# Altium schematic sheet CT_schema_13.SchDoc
size 388 x 278 mm
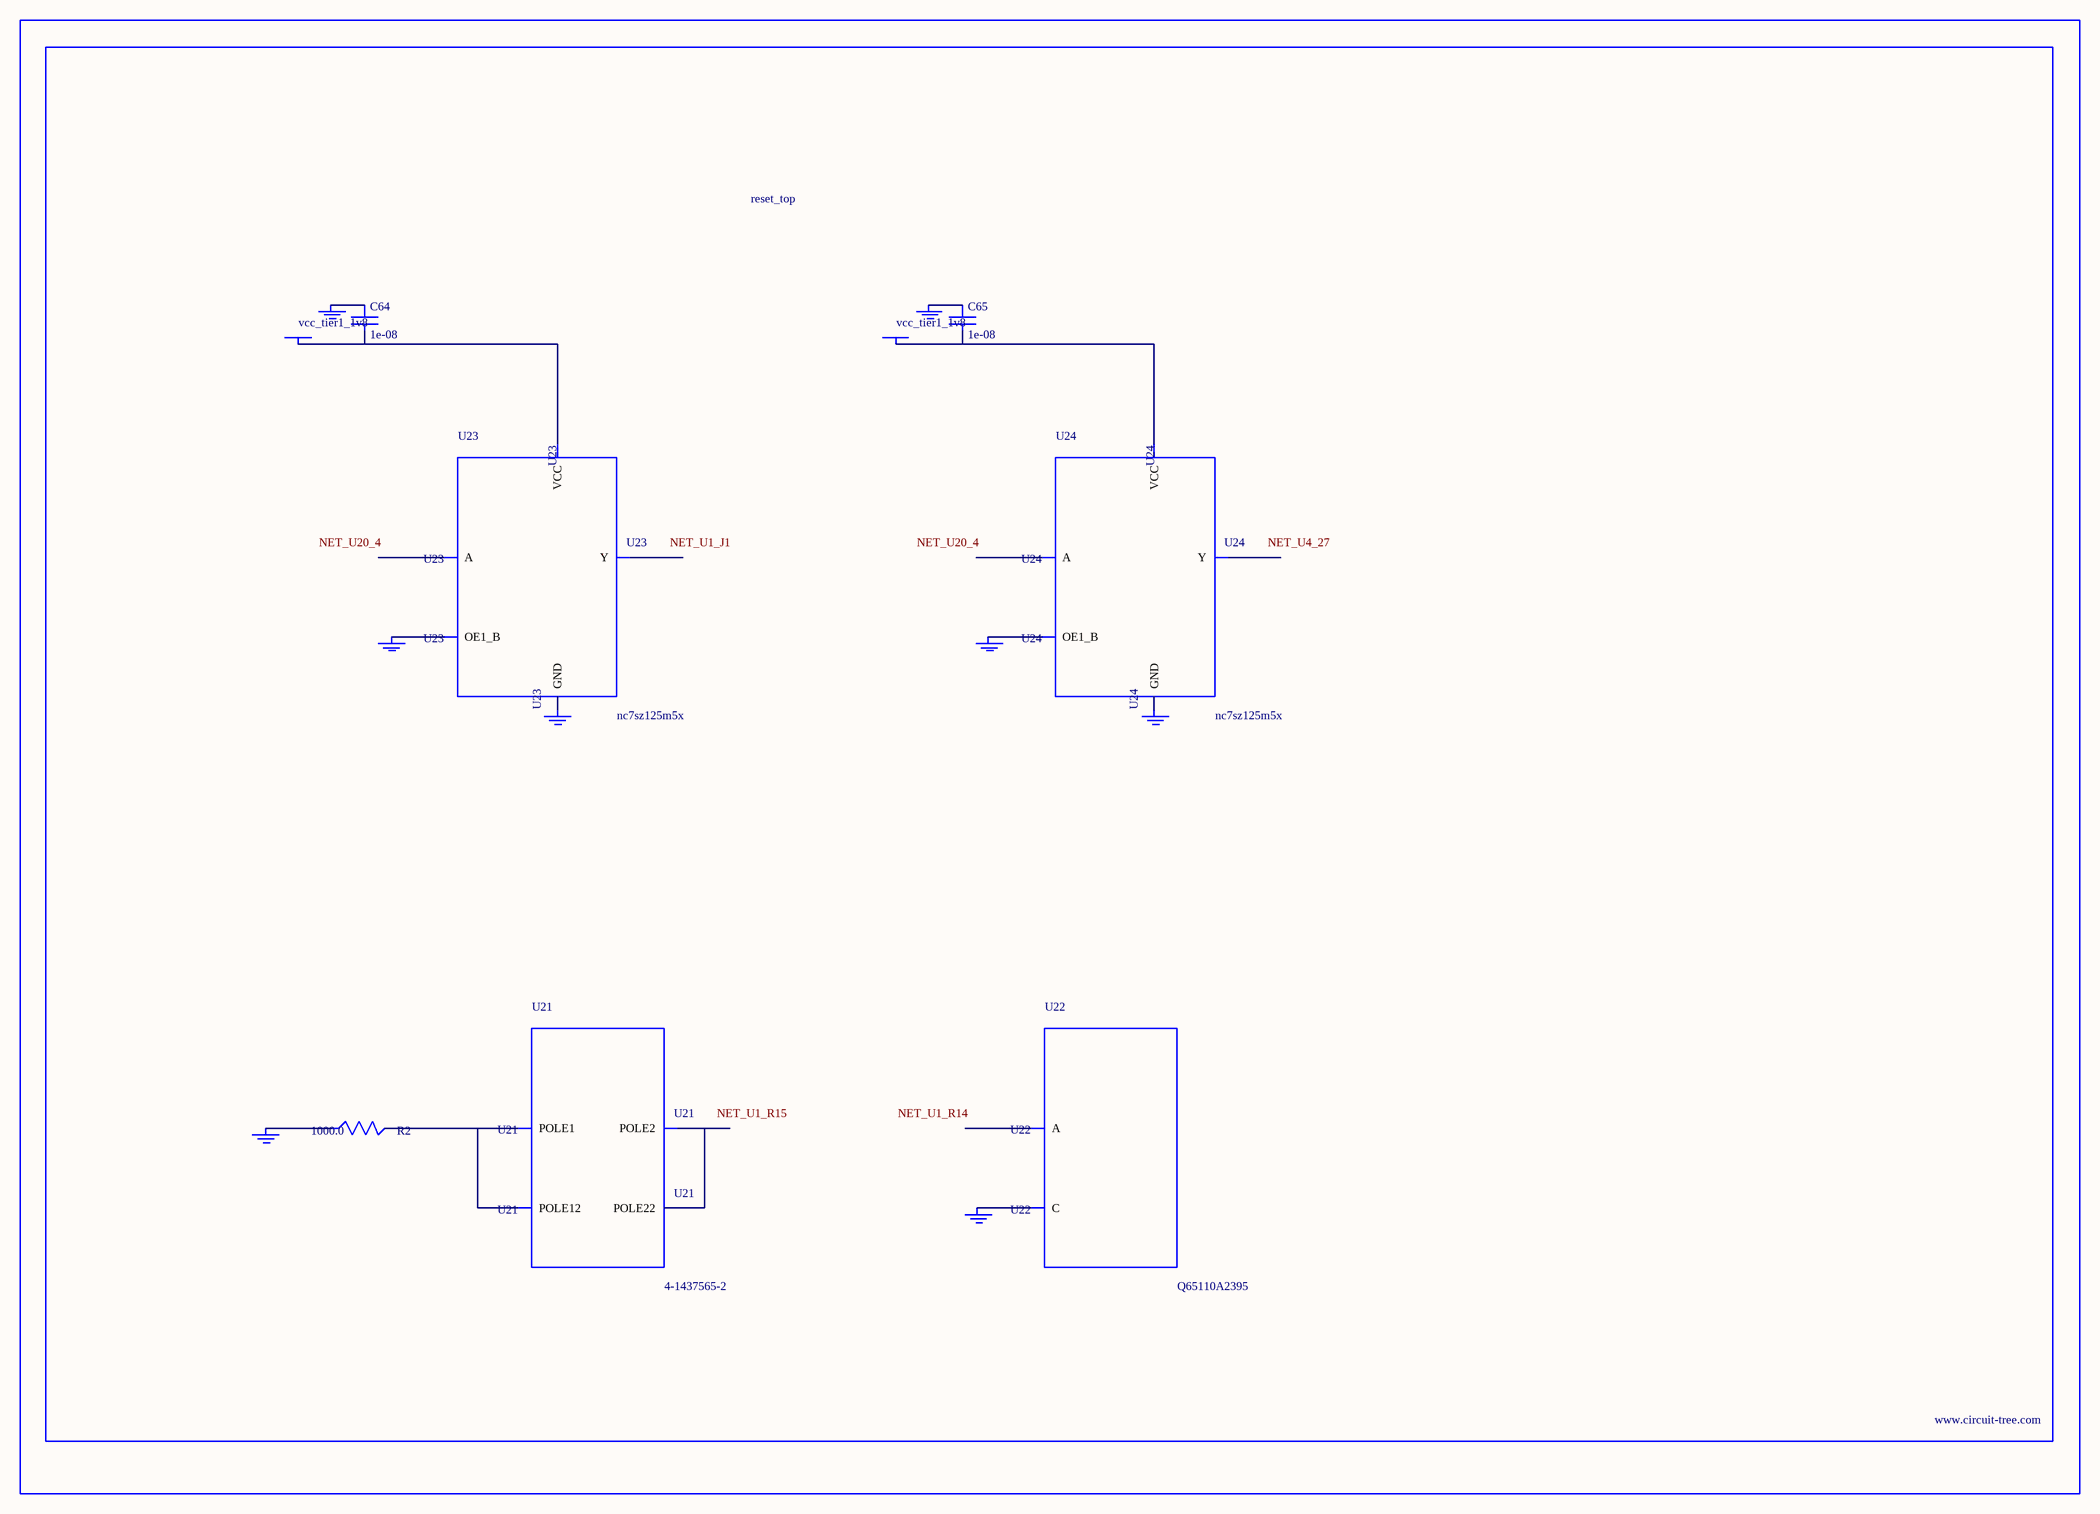
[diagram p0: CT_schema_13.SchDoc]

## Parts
BORDER12  (no value)
C64  1e-08  [C0402]
C65  1e-08  [C0402]
GND_INSTANCE_12_0  (no value)
GND_INSTANCE_12_1  (no value)
GND_INSTANCE_12_2  (no value)
GND_INSTANCE_12_3  (no value)
GND_INSTANCE_12_4  (no value)
GND_INSTANCE_12_5  (no value)
GND_INSTANCE_12_6  (no value)
GND_INSTANCE_12_7  (no value)
POWER_INSTANCE_12_0  vcc_tier1_1v8
POWER_INSTANCE_12_1  vcc_tier1_1v8
R2  1000.0  [R0603]
U21  4-1437565-2  [SW_4-1437565-2]
U22  Q65110A2395  [LGM67K-G1J2-24-Z]
U23  nc7sz125m5x  [NC7SZ125M5X]
U24  nc7sz125m5x  [NC7SZ125M5X]

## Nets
NetC64_1: C64.1 GND_INSTANCE_12_2.0(GND)
NetC64_2: C64.2 POWER_INSTANCE_12_0.0(PWR) U23.5(VCC)
NetC65_1: C65.1 GND_INSTANCE_12_5.0(GND)
NetC65_2: C65.2 POWER_INSTANCE_12_1.0(PWR) U24.5(VCC)
NetGND_INSTANCE_12_0_0: GND_INSTANCE_12_0.0(GND) R2.1
NetGND_INSTANCE_12_1_0: GND_INSTANCE_12_1.0(GND) U22.C
NetGND_INSTANCE_12_3_0: GND_INSTANCE_12_3.0(GND) U23.1(OE1_B)
NetGND_INSTANCE_12_4_0: GND_INSTANCE_12_4.0(GND) U23.3(GND)
NetGND_INSTANCE_12_6_0: GND_INSTANCE_12_6.0(GND) U24.1(OE1_B)
NetGND_INSTANCE_12_7_0: GND_INSTANCE_12_7.0(GND) U24.3(GND)
NetR2_2: R2.2 U21.1(POLE1) U21.2(POLE12)
NetU21_3: U21.3(POLE2) U21.4(POLE22)

Not connected (* = marked no-connect by the designer): U22 A; U23 2(A) 4(Y); U24 2(A) 4(Y)

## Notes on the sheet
- Labels drawn without touching a wire or pin: NET_U1_J1, NET_U1_R14, NET_U1_R15, NET_U4_27, NET_U20_4

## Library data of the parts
BORDER12 = BORDER_PAGE12
C64 C65 = C0402C103K3RAC
GND_INSTANCE_12_0-GND_INSTANCE_12_7 = GND
POWER_INSTANCE_12_0 POWER_INSTANCE_12_1 = PWR
R2 = RC0603JR-071KL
